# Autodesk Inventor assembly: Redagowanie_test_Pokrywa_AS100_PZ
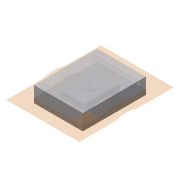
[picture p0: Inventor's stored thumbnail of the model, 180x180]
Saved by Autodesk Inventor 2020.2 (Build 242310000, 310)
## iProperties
Created: 2015-11
Part Number: Redagowanie_test_Pokrywa_AS100_PZ
Document SubType Name: Assembly
Designer: F.Stasiak
Catalog Web Link: www.expertbooks.pl
Manager: www.cadconsulting.pl
Company: Fabian Stasiak CAD Consulting
Author: F.Stasiak
Subject: Zbiór ćwiczeń. Autodesk Inventor 2020. Kurs Professional
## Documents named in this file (7)
- C:\2020_Kurs_Professional\R6 Formy\Redagowanie\Redagowanie_test_Pokrywa_AS100_PZ.iam
- C:\2020_Kurs_Professional\R6 Formy\Redagowanie\Redagowanie_test_Pokrywa_AS100_MP.ipt
- C:\2020_Kurs_Professional\R6 Formy\Redagowanie\Redagowanie_test_Pokrywa_AS100_WP.ipt
- C:\2020_Kurs_Professional\R6 Formy\Redagowanie\Redagowanie_test_Pokrywa_AS100_CR_Base.ipt
- C:\2020_Kurs_Professional\R6 Formy\Redagowanie\Redagowanie_test_Pokrywa_AS100_CR_1.ipt
- C:\2020_Kurs_Professional\R6 Formy\Redagowanie\Redagowanie_test_Pokrywa_AS100_CV_Base.ipt
- C:\2020_Kurs_Professional\R6 Formy\Redagowanie\Redagowanie_test_Pokrywa_AS100_CV_1.ipt
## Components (6 placed, 6 different names)
1. Redagowanie_test_Pokrywa_AS100_MP:1 — Równoległy:1, Równoległy:2, Równoległy:3, Równoległy:4, Równoległy:5, Równoległy:6
2. Redagowanie_test_Pokrywa_AS100_WP:1 — Równoległy:4, Równoległy:5, Równoległy:6
3. Redagowanie_test_Pokrywa_AS100_CR_Base:1 — Równoległy:7, Równoległy:8, Równoległy:9, Równoległy:13, Równoległy:14, Równoległy:15
4. Redagowanie_test_Pokrywa_AS100_CR_1:1 — Równoległy:13, Równoległy:14, Równoległy:15
5. Redagowanie_test_Pokrywa_AS100_CV_Base:1 — Równoległy:10, Równoległy:11, Równoległy:12, Równoległy:16, Równoległy:17, Równoległy:18
6. Redagowanie_test_Pokrywa_AS100_CV_1:1 — Równoległy:16, Równoległy:17, Równoległy:18
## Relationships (18: Flush 18)
- Równoległy:1 [Flush]: Redagowanie_test_Pokrywa_AS100_MP:1
- Równoległy:2 [Flush]: Redagowanie_test_Pokrywa_AS100_MP:1
- Równoległy:3 [Flush]: Redagowanie_test_Pokrywa_AS100_MP:1
- Równoległy:4 [Flush]: Redagowanie_test_Pokrywa_AS100_MP:1 ↔ Redagowanie_test_Pokrywa_AS100_WP:1
- Równoległy:5 [Flush]: Redagowanie_test_Pokrywa_AS100_MP:1 ↔ Redagowanie_test_Pokrywa_AS100_WP:1
- Równoległy:6 [Flush]: Redagowanie_test_Pokrywa_AS100_MP:1 ↔ Redagowanie_test_Pokrywa_AS100_WP:1
- Równoległy:7 [Flush]: Redagowanie_test_Pokrywa_AS100_CR_Base:1
- Równoległy:8 [Flush]: Redagowanie_test_Pokrywa_AS100_CR_Base:1
- Równoległy:9 [Flush]: Redagowanie_test_Pokrywa_AS100_CR_Base:1
- Równoległy:10 [Flush]: Redagowanie_test_Pokrywa_AS100_CV_Base:1
- Równoległy:11 [Flush]: Redagowanie_test_Pokrywa_AS100_CV_Base:1
- Równoległy:12 [Flush]: Redagowanie_test_Pokrywa_AS100_CV_Base:1
- Równoległy:13 [Flush]: Redagowanie_test_Pokrywa_AS100_CR_Base:1 ↔ Redagowanie_test_Pokrywa_AS100_CR_1:1
- Równoległy:14 [Flush]: Redagowanie_test_Pokrywa_AS100_CR_Base:1 ↔ Redagowanie_test_Pokrywa_AS100_CR_1:1
- Równoległy:15 [Flush]: Redagowanie_test_Pokrywa_AS100_CR_Base:1 ↔ Redagowanie_test_Pokrywa_AS100_CR_1:1
- Równoległy:16 [Flush]: Redagowanie_test_Pokrywa_AS100_CV_Base:1 ↔ Redagowanie_test_Pokrywa_AS100_CV_1:1
- Równoległy:17 [Flush]: Redagowanie_test_Pokrywa_AS100_CV_Base:1 ↔ Redagowanie_test_Pokrywa_AS100_CV_1:1
- Równoległy:18 [Flush]: Redagowanie_test_Pokrywa_AS100_CV_Base:1 ↔ Redagowanie_test_Pokrywa_AS100_CV_1:1
